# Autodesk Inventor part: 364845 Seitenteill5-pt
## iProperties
Company: Hundt & Weber AG Schaltgeräte
Created: 2010-11
Part Number: 364845 Seitenteill5-pt
Material: 1.0120
Document SubType Name: Modeling
Designer: I.Baliuc
Manufacturer: Standard
Standards Organization: Custom
Description: Seitenteil, Trenner
Cost Center: 5,196 kg
Authority: 661896 mm^3
Density: 7.85 g/cm^3
HalbzeugNorm: DIN 174
Zweck: HSLT / HSE - Standardseite
Abmessung: Fl. 120x12-170
SaveDate: 2006-10-28
SaveTime: 20:23
TotalMass: 5,196 kg
TotalVolume: 661896 mm^3
Author: AHausen
Revision Number: 364845
Keywords: 380125
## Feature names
1. Extrusion2
2. Bohrung_Ø13 [Hole]
3. Bohrung2 [Hole]
4. Bohrung3 [Hole]
5. Bohrung_M8_01 [Hole]
6. Bohrung_M8_02 [Hole]
7. Bohrung_M6 [Hole]
8. Bohrung_M5 [Hole]
9. Neue Bohrung (zusätzlich) [Rectangular Pattern]
